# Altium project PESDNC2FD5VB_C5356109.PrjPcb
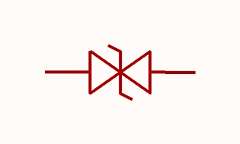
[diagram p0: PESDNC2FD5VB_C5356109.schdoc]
1 sheet, 1 parts. Net scope: global (net labels, ports and power ports of the same name join across sheets).

## Sheet PESDNC2FD5VB_C5356109.schdoc
size 127 x 101 mm

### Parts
U?  pesdnc2fd5vb_c5356109  [X1-DFN1006-2_L1.0-W0.6-P0.65-BI]  (value not drawn)

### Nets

Not connected (* = marked no-connect by the designer): U? 1(C) 2(A)

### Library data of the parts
U? = pesdnc2fd5vb_c5356109: 极性:双向;反向截止电压(Vrwm):5V;钳位电压:17V;峰值脉冲电流(Ipp):5A;峰值脉冲功率(Ppp):68W;击穿电压(VBR):5.7V;; Manufacturer: JSMSEMI(杰盛微); AddInBom: yes; ModelId: e1a2843302f940e8ac07b7d637792d48; ModelTransform: 39.37,23.622,0,0,0,0,0,0,0; Polarity: 双向; Reverse Stand-Off Voltage (Vrwm): 5V; Clamping Voltage: 17V; Peak Pulse Current (Ipp): 5A; Peak Pulse Power Dissipation (Ppp): 68W; Voltage - Breakdown: 5.7V; Reverse Leakage Current (Ir): 100nA; Number of Channels: 单路; level of protection: IEC 61000-4-2; Junction Capacitance: 8.9pF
